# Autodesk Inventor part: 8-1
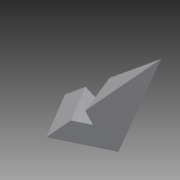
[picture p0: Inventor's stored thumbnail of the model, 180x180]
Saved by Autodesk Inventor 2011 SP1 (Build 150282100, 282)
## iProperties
Created: 2014-01
Part Number: 8-1
Document SubType Name: Modeling
Designer: Administrator
Density: 1 g/cm^3
Author: Administrator
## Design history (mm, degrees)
sketch "草图1"
  geometry: L1 (-37.416, -3.202)-(-2.809, -13.652); L2 (-2.809, -13.652)-(-24.882, -24.222); L3 (-24.882, -24.222)-(-37.416, -3.202); 1 further point
  constraints: 6 end point
sketch "草图2"
  geometry: 2 further points
feature "放样1" sketch "草图1", "草图2" dims "d0" = 0, "d1" = 90 deg, "d2" = 0, "d3" = 90 deg
sketch "草图3"
  geometry: L1 (-3.027, 32.602)-(37.416, 0) reference; L2 (-3.027, 32.602)-(24.882, 0) reference; L3 (37.416, 0)-(2.809, 0) reference; L4 (12.17, 6.956)-(28.786, 6.956); L5 (12.17, 6.956)-(18.715, 15.075); 1 further point
  constraints: 4 end point, 2 point on line, 1 parallel, 1 perpendicular
extrude "拉伸1" cut sketch "草图3" stored distance "d4" = 10; taper "d5" = 0 deg
node "实体1"
